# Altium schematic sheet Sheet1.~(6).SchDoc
size A; SheetNumber: 1; SheetTotal: 1
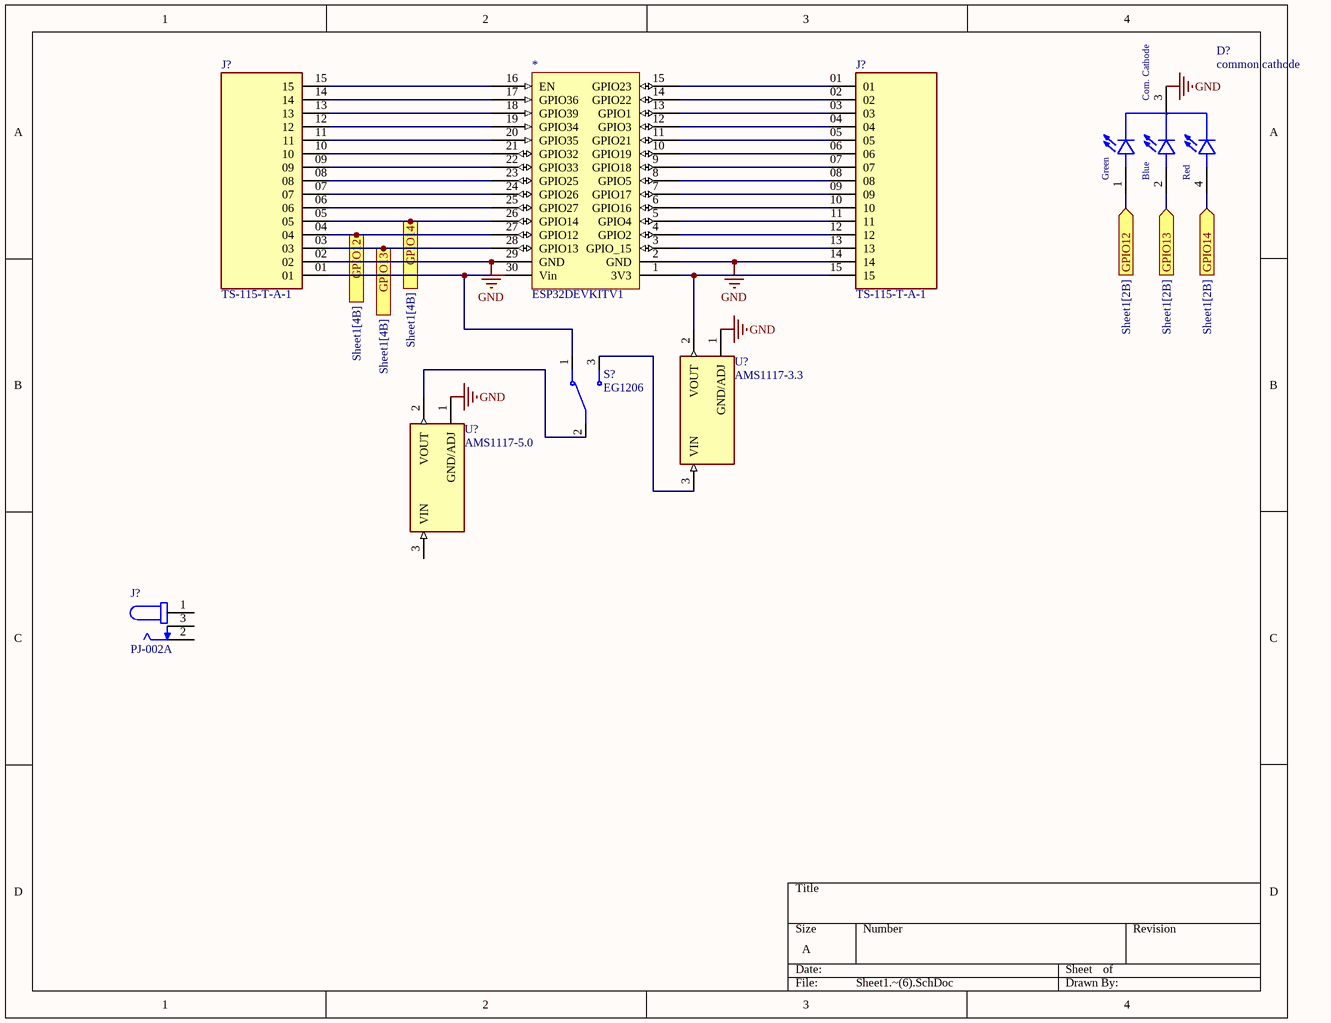
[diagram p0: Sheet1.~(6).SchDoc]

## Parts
(Parts that share a designator on the sheet are numbered #1, #2 ... from top to bottom, then left to right.)
*  ESP32DEVKITV1  [ESP32DEVKITV1]
D?  common cathode  [LED RGB 5mm]
J?#1  TS-115-T-A-1  [SAMTEC_TS-115-T-A-1]
J?#2  TS-115-T-A-1  [SAMTEC_TS-115-T-A-1]
J?#3  PJ-002A  [CUI_PJ-002A]
S?  EG1206  [SW_EG1206]
U?#1  AMS1117-3.3  [SOT229P700X180-4N]
U?#2  AMS1117-5.0  [SOT229P700X180-4N]

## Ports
GPIO12 (in, see Sheet1[2B]), GPIO12 (out, see Sheet1[4B]), GPIO13 (in, see Sheet1[2B]), GPIO13 (out, see Sheet1[4B]), GPIO14 (in, see Sheet1[2B]), GPIO14 (out, see Sheet1[4B])

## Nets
GND: *.2(GND) *.29(GND) D?.3(Com._Cathode) J?#1.02 J?#2.14 U?#1.1(GND/ADJ) U?#2.1(GND/ADJ)
GPIO12: *.27(GPIO12) D?.1(Green) J?#1.04 ; port GPIO12
GPIO13: *.28(GPIO13) D?.2(BLUE) J?#1.03 ; port GPIO13
GPIO14: *.26(GPIO14) D?.4(Red) J?#1.05 ; port GPIO14
Net*_1: *.1(3V3) J?#2.15 U?#1.2(VOUT)
Net*_3: *.3(GPIO_15) J?#2.13
Net*_4: *.4(GPIO2) J?#2.12
Net*_5: *.5(GPIO4) J?#2.11
Net*_6: *.6(GPIO16) J?#2.10
Net*_7: *.7(GPIO17) J?#2.09
Net*_8: *.8(GPIO5) J?#2.08
Net*_9: *.9(GPIO18) J?#2.07
Net*_10: *.10(GPIO19) J?#2.06
Net*_11: *.11(GPIO21) J?#2.05
Net*_12: *.12(GPIO3) J?#2.04
Net*_13: *.13(GPIO1) J?#2.03
Net*_14: *.14(GPIO22) J?#2.02
Net*_15: *.15(GPIO23) J?#2.01
Net*_16: *.16(EN) J?#1.15
Net*_17: *.17(GPIO36) J?#1.14
Net*_18: *.18(GPIO39) J?#1.13
Net*_19: *.19(GPIO34) J?#1.12
Net*_20: *.20(GPIO35) J?#1.11
Net*_21: *.21(GPIO32) J?#1.10
Net*_22: *.22(GPIO33) J?#1.09
Net*_23: *.23(GPIO25) J?#1.08
Net*_24: *.24(GPIO26) J?#1.07
Net*_25: *.25(GPIO27) J?#1.06
Net*_30: *.30(Vin) J?#1.01 S?.1
NetS?_2: S?.2 U?#2.2(VOUT)
NetS?_3: S?.3 U?#1.3(VIN)

Not connected (* = marked no-connect by the designer): J?#3 1 2 3; U?#2 3(VIN)

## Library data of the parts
D? = LED RGB 5mm: MF: {'manufacturer': u'Kingbright'}; MP: WP154A4SUREQBFZGC
J?#1 J?#2 = TS-115-T-A-1: MF: {'manufacturer': u'Samtec'}
J?#3 = PJ-002A: 2.0 mm Center Pin, 2.5 A, Right Angle, Through Hole, Dc Power Jack Connector; MF: {'manufacturer': u'CUI Devices'}
S? = EG1206: MF: {'manufacturer': u'E-Switch'}
U?#1 = AMS1117-3.3: MF: {'manufacturer': u'Advanced Monolithic Systems'}
U?#2 = AMS1117-5.0: MF: {'manufacturer': u'Advanced Monolithic Systems'}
